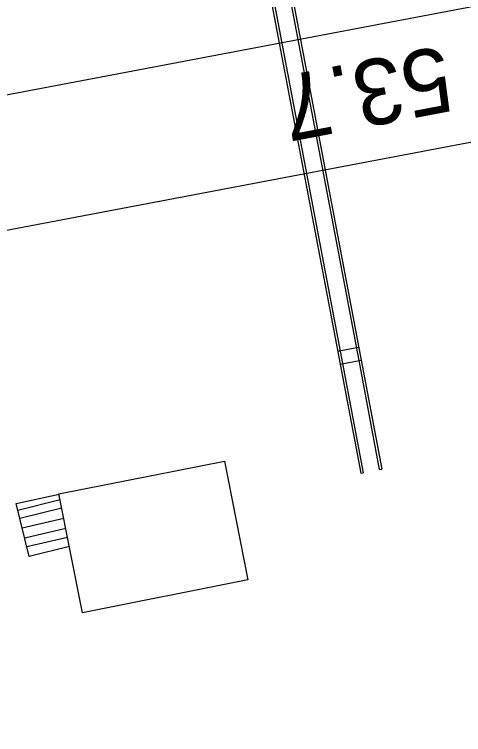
# Model space of a CAD drawing. Extents: x 6541740 to 6566395, y 5525066 to 5530361.
# Drawn here: x 6559101.69 to 6559115.36, y 5526506.98 to 5526528.87 of the extents above; entities that cross this region are included whole.
import ezdxf

# ---------------------------------------------------------------- set-up
doc = ezdxf.new("R2010")
doc.units = 0
for name, color, linetype in [('ps_wymiarowanie', 7, 'Continuous'), ('TOR_PRZEK_P-komponent', 7, 'Continuous'), ('TOR_RAMKI-ramka+tabelka 1', 7, 'Continuous'), ('TOR_W-warstwa dodatkowa 2', 7, 'Continuous')]:
    doc.layers.add(name, color=color, linetype=linetype)

msp = doc.modelspace()

# ---------------------------------------------------------------- linework, layer by layer
at = {"layer": 'ps_wymiarowanie'}
for p, q in [((6559103.082, 5526514.11), (6559101.794, 5526513.79)), ((6559101.851, 5526513.56), (6559103.129, 5526513.87)), ((6559101.925, 5526513.267), (6559103.192, 5526513.556)), ((6559102.002, 5526512.956), (6559103.253, 5526513.248)), ((6559102.067, 5526512.698), (6559103.307, 5526512.978))]:
    msp.add_line(p, q, dxfattribs=at)
msp.add_lwpolyline([(6559103.046, 5526514.294), (6559108.078, 5526515.292), (6559108.794, 5526511.679), (6559103.762, 5526510.681)], close=True, dxfattribs=at)
msp.add_lwpolyline([(6559103.362, 5526512.698), (6559102.143, 5526512.393), (6559101.741, 5526514.003), (6559103.047, 5526514.286)], dxfattribs=at)
at = {"layer": 'TOR_PRZEK_P-komponent'}
for p, q in [((6559263.549, 5526557.147), (6557908.193, 5526300.236)), ((6559264.303, 5526553.168), (6558036.172, 5526320.373))]:
    msp.add_line(p, q, dxfattribs=at)
at = {"layer": 'TOR_W-warstwa dodatkowa 2'}
for p, q in [((6559108.38, 5526538.314), (6559112.165, 5526518.347)), ((6559108.38, 5526538.314), (6559112.165, 5526518.347)), ((6559107.889, 5526538.221), (6559111.673, 5526518.254)), ((6559107.889, 5526538.221), (6559111.673, 5526518.254)), ((6559108.528, 5526537.935), (6559112.238, 5526518.361)), ((6559108.528, 5526537.935), (6559112.238, 5526518.361)), ((6559107.889, 5526537.814), (6559111.6, 5526518.24)), ((6559107.889, 5526537.814), (6559111.6, 5526518.24)), ((6559111.525, 5526518.633), (6559112.164, 5526518.754)), ((6559111.525, 5526518.633), (6559112.164, 5526518.754)), ((6559111.6, 5526518.24), (6559112.238, 5526518.361)), ((6559111.6, 5526518.24), (6559112.238, 5526518.361)), ((6559111.6, 5526518.24), (6559112.228, 5526514.924)), ((6559111.6, 5526518.24), (6559112.228, 5526514.924)), ((6559111.673, 5526518.254), (6559112.302, 5526514.938)), ((6559111.673, 5526518.254), (6559112.302, 5526514.938)), ((6559112.165, 5526518.347), (6559112.793, 5526515.031)), ((6559112.165, 5526518.347), (6559112.793, 5526515.031)), ((6559112.238, 5526518.361), (6559112.867, 5526515.045)), ((6559112.238, 5526518.361), (6559112.867, 5526515.045)), ((6559112.228, 5526514.924), (6559112.302, 5526514.938)), ((6559112.228, 5526514.924), (6559112.302, 5526514.938)), ((6559112.793, 5526515.031), (6559112.867, 5526515.045)), ((6559112.793, 5526515.031), (6559112.867, 5526515.045))]:
    msp.add_line(p, q, dxfattribs=at)

# ---------------------------------------------------------------- texts
at = {"layer": 'TOR_RAMKI-ramka+tabelka 1'}
msp.add_text('53.7', height=2, rotation=190.7691, dxfattribs=at).set_placement((6559114.774, 5526527.929))

doc.saveas('drawing.dxf')
